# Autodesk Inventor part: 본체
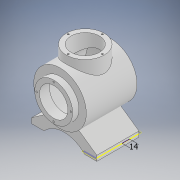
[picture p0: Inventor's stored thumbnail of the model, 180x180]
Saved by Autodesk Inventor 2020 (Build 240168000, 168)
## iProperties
Created: 2023-12
Part Number: 본체
Material: 일반
Document SubType Name: Modeling
Designer: 1강의실14
Density: 1 g/cm^3
Appearance: 기본값
Author: 1강의실14
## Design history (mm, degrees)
sketch "스케치1"
  geometry: 1 further point
sketch "스케치2"
  geometry: L1 (0, 60)-(0, -60); L2 (27, 60)-(27, 41); L3 (27, 41)-(43, 41); L4 (43, 41)-(43, -43.887); L5 (27, 60)-(36, 60); L6 (36, 60)-(36, 48); L7 (36, 48)-(50, 48); L8 (50, 48)-(50, -48.336); L9 (0, -53)-(0, -60); A1 r 113 centre (0, 53) between (0, -60) and (50, -48.336); A2 r 106 centre (0, 53) between (0, -53) and (43, -43.887); 3 further points
  constraints: 18 end point, 5 perpendicular, 4 point on circle, 2 centre point, 2 vertical, 1 coincident, 1 collinear, 1 horizontal, 1 midpoint, 1 vertical alignment
  dimensions: "d0" = 120 distance of L1.start L1.end; "d2" = 54 diameter of L2 L1; "d3" = 72 diameter of L6 L1; "d4" = 86 diameter of L4 L1; "d5" = 100 diameter of L8 L1; "d7" = 113 radius of A1; "d8" = 7 radial gap between concentric circles of A1 A2; "d9" = 19 distance of L2.start L2.end; "d10" = 41 distance from line of point (0, 0) L3; "d11" = 48 distance from line of L7 point (0, 0)
revolve "회전1" sketch "스케치2" stored, may be unused: angle "d12" = 90 deg
node "작업 평면1"
sketch "스케치3"
  geometry: C1 r 36 at (0, 0); 1 further point
  constraints: 1 centre point, 1 coincident
  dimensions: "d14" = 72 diameter of C1
extrude "돌출1" join sketch "스케치3" stored distance "d15" = 10; taper "d16" = 0 deg; dims "d13" = 65
sketch "스케치4"
  geometry: C1 r 27 at (0, 0); 1 further point
  constraints: 1 centre point, 1 coincident
  dimensions: "d17" = 54 diameter of C1
extrude "돌출2" cut sketch "스케치4" stored distance "d18" = 10; taper "d19" = 0 deg; dims "d13" = 65
node "작업 평면2"
sketch "스케치5"
  geometry: L1 (-62, -77)-(-38.5, -77); L2 (-62, -77)-(-62, -67); L3 (-62, -67)-(-16.129, -34.881); L4 (-16.129, -34.881)-(16.129, -34.881); L5 (16.129, -34.881)-(62, -67); L6 (62, -67)-(62, -77); L7 (62, -77)-(38.5, -77); A1 r 52.096 centre (0, -112.096) between (38.5, -77) and (-38.5, -77); A2 r 50 centre (0, 0) between (-26.694, -42.278) and (26.694, -42.278); 5 further points
  constraints: 14 end point, 5 horizontal alignment, 5 point on circle, 3 midpoint, 3 vertical alignment, 2 centre point, 2 equal length, 2 perpendicular, 2 point on line, 1 coincident, 1 horizontal, 1 parallel, 1 vertical
  dimensions: "d21" = 77 distance of L1.end L7.end; "d22" = 10 distance of L5.end L6.end; "d23" = 55 deg angle of L5 L6; "d24" = 17 distance edge to line of A1 L7; "d25" = 77 distance from line of point (0, 0) L7; "d26" = 34.88093 distance from line of point (0, 0) L4; "d27" = 124 distance of L1.start L6.end; "d28" = 100 diameter of A2
extrude "돌출3" join sketch "스케치5" distance "d29" = 80; taper "d30" = 0 deg
sketch "스케치6" dims "d38" = 65
  geometry: L1 (0, 0)-(0, 32.5); 1 further point
  constraints: 2 end point, 1 coincident, 1 vertical, 1 vertical alignment, 2 other
hole "구멍1" sketch "스케치6" at (0, 32.5) diameter "d31" = 3.242; stored, may be unused: countersink angle "d35" = 90 deg, drill point angle "d37" = 118 deg; dims "d32" = 8, "d33" = 4, "d34" = 2, "d36" = 10
sketch "스케치7" dims "d49" = 65
  geometry: L1 (0, 0)-(0, 32.5); 1 further point
  constraints: 2 end point, 1 coincident, 1 vertical, 1 vertical alignment, 2 other
hole "구멍2" sketch "스케치7" at (0, 32.5) diameter "d42" = 3.242; stored, may be unused: countersink angle "d46" = 90 deg, drill point angle "d48" = 118 deg; dims "d43" = 8, "d44" = 4, "d45" = 2, "d47" = 10
node "작업 평면3"
sketch "스케치8"
  geometry: L1 (23.5, 0)-(23.5, -80) reference; L2 (23.5, -61.718)-(13.568, -61.718); L3 (23.5, -47.718)-(13.568, -47.718); L4 (23.5, -47.718)-(23.5, -61.718); A1 r 7 centre (13.568, -54.718) between (13.568, -47.718) and (13.568, -61.718); 1 further point
  constraints: 6 end point, 2 horizontal, 2 point on circle, 2 point on line, 2 tangent, 1 centre point, 1 collinear
  dimensions: "d55" = 14 distance between parallel lines of L3 L2
node "솔리드1"
pattern_circular "원형 패턴1" dims angle "d40" = 360 deg
pattern_circular "원형 패턴2" dims angle "d51" = 360 deg
feature "A9D066F2-1C7D-4E18-AEED-F7BC21143FA4" dims "d31" = 3.242, "d32" = 8, "d33" = 4, "d34" = 2, "d35" = 90 deg, "d36" = 10, "d37" = 118 deg
other parameters: "d53" = -6
